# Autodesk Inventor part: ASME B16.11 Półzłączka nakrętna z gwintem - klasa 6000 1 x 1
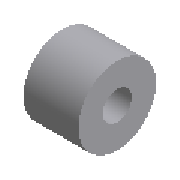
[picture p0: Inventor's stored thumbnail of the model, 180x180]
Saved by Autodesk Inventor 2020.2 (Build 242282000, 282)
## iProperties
Manager: www.cadconsulting.pl
Company: Fabian Stasiak CAD Consulting
NAME: PIPING: ASME B16.11 Half Coupling Threaded - Class 6000
DATA: <meta><inlinegroups number="1" deflen="6.0325"></inlinegroups><connections number="2"></connections><angles><a>3.14159265358979</a></angles></meta>
IsCustomPart: 0
Created: 2014-02
Part Number: ASME B16.11 Półzłączka nakrętna z gwintem - klasa 6000 1 x 1
Material: Stal
Description: Złączka połówkowa, gwintowana - klasa 6000
Document SubType Name: Modeling
Standard: ASME B16.11
Designer: F.Stasiak
Standard Revision: 2005
Standards Organization: ANSI
Language: pl-PL
Size Designation: 1 x 1
Categories: <MemberInstance><Categories><Category DisplayName="Rury cienko- i grubościenne" InternalName="4347fa0f-2144-441d-94cd-e3e15c92b736" Mnemonic="TUBEANDPIPE"><Cate
Density: 1 g/cm^3
Appearance: Płyta
Catalog Web Link: www.expertbooks.pl
Author: F.Stasiak
Subject: Zbiór ćwiczeń. Autodesk Inventor 2020. Kurs Professional
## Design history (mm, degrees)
sketch "Sketch1"
  geometry: L1 (0, 0)-(30.226, 0); L2 (30.226, 0)-(30.226, 14.305); L3 (30.226, 14.305)-(17.343, 14.305); L4 (17.343, 14.305)-(0, 14.847); L5 (0, 14.847)-(0, 0); L6 (30.226, 28.575)-(0, 28.575); L7 (0, 28.575)-(0, 14.847); L8 (30.226, 28.575)-(30.226, 14.305); L9 (17.343, 14.305)-(17.343, 0)
  constraints: 18 end point, 3 parallel, 3 perpendicular, 1 horizontal, 1 point on line, 1 vertical
  dimensions: "d0" = 29.69412 diameter of L4.end L1 (= MD); "d1" = 57.15 diameter of L6.end L1 (= D); "d2" = 30.226 distance of L6.start L6.end (= 0.5 x W1); "d3" = 1.78991 deg angle of L1 L4; "d4" = 17.34312 horizontal distance of L3.end L4.end (= L)
revolve "Revolve1" stored, may be unused: angle "d6" = 90 deg
workpoint "Work Point2"
workaxis "Work Axis2"
workpoint "Work Point3"
workaxis "Work Axis3"
workpoint "Work Point4"
body "Solid1"
feature "Gwint1" dims "d16" = 25.4, "d17" = 0
other parameters: "W1" = 60.452 [user parameter; used in 1 equation term], "D" = 57.15 [user parameter; used in 1 equation term], "L" = 17.34312 [user parameter; used in 1 equation term], "MD" = 29.69412 [user parameter; used in 1 equation term], "Size_Designation" = 12.345 [user parameter]
